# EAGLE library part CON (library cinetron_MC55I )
Konektor pro GSM modul MC55i samicka (na BRD)
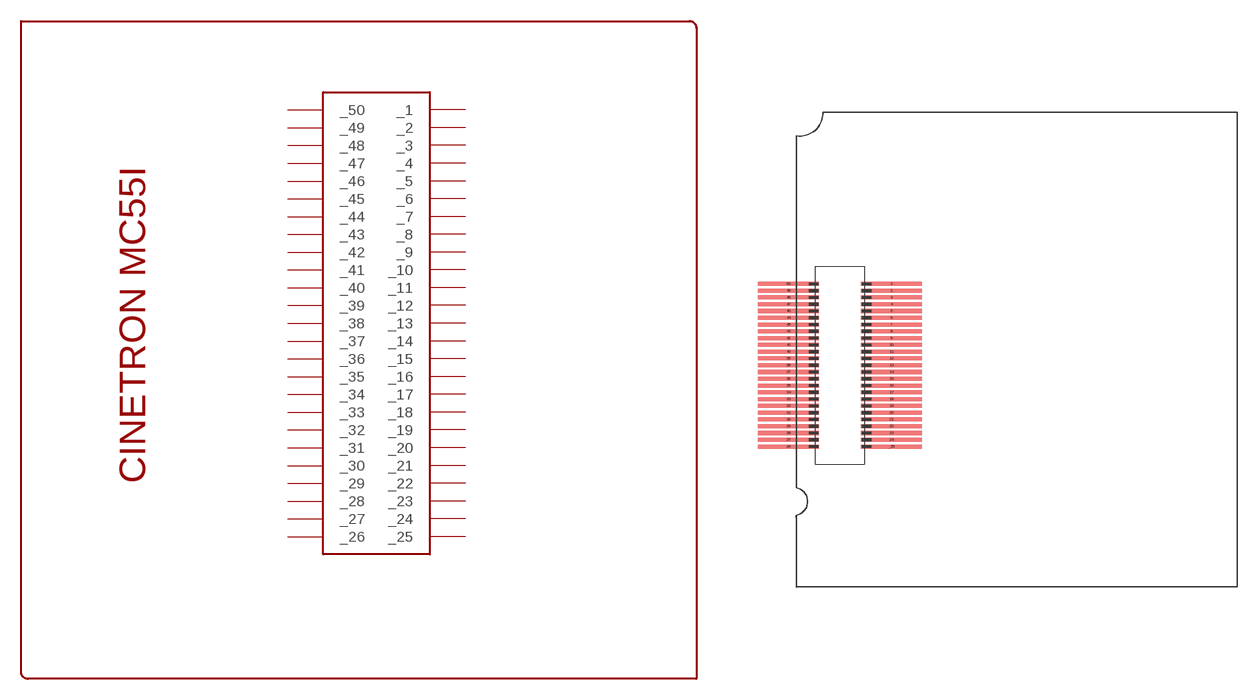
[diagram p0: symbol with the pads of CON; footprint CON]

Designator prefix -

## CON  [CON]
1  _1
2  _2
3  _3
4  _4
5  _5
6  _6
7  _7
8  _8
9  _9
10  _10
11  _11
12  _12
13  _13
14  _14
15  _15
16  _16
17  _17
18  _18
19  _19
20  _20
21  _21
22  _22
23  _23
24  _24
26  _26
27  _27
28  _28
29  _29
30  _30
31  _31
32  _32
33  _33
34  _34
35  _35
36  _36
37  _37
38  _38
39  _39
40  _40
41  _41
42  _42
43  _43
44  _44
45  _45
46  _46
47  _47
48  _48
49  _49
50  _50
_25  _25

## Footprint CON (pad centres in mm)
smd 4.5 x 0.3: 1 3.8,6.05; 2 3.8,5.55; 3 3.8,5.05; 4 3.8,4.55; 5 3.8,4.05; 6 3.8,3.55; 7 3.8,3.05; 8 3.8,2.55; 9 3.8,2.05; 10 3.8,1.55; 11 3.8,1.05; 12 3.8,0.55; 13 3.8,0.05; 14 3.8,-0.45; 15 3.8,-0.95; 16 3.8,-1.45; 17 3.8,-1.95; 18 3.8,-2.45; 19 3.8,-2.95; 20 3.8,-3.45; 21 3.8,-3.95; 22 3.8,-4.45; 23 3.8,-4.95; 24 3.8,-5.45; 26 -3.8,-5.95; 27 -3.8,-5.45; 28 -3.8,-4.95; 29 -3.8,-4.45; 30 -3.8,-3.95; 31 -3.8,-3.45; 32 -3.8,-2.95; 33 -3.8,-2.45; 34 -3.8,-1.95; 35 -3.8,-1.45; 36 -3.8,-0.95; 37 -3.8,-0.45; 38 -3.8,0.05; 39 -3.8,0.55; 40 -3.8,1.05; 41 -3.8,1.55; 42 -3.8,2.05; 43 -3.8,2.55; 44 -3.8,3.55; 45 -3.8,3.05; 46 -3.8,4.05; 47 -3.8,4.55; 48 -3.8,5.05; 49 -3.8,5.55; 50 -3.8,6.05; _25 3.8,-5.95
